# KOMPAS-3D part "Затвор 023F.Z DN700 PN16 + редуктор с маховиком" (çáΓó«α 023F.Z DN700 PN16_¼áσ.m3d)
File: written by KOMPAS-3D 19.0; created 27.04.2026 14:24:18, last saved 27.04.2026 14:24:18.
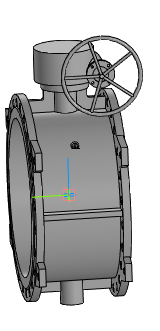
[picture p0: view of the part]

Document properties: Полное имя файла: ..\..\Затвор 023F.Z DN200-DN1600_с маховиком\Затвор 023F.Z DN700 PN16 + редуктор с маховиком.a3d

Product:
- Part/product: Затвор 023F.Z DN700 PN16 + редуктор с маховиком
    Масса: 595.522

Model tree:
1. Операция без истории:1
